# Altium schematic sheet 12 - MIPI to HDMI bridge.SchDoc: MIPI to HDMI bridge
size A3; PageSetup: Record=PageOptions¦CenterHorizontal=True¦CenterVertical=True¦PrintScale=0.70¦XCorrection=1.00¦YCorrection=1.00¦PrintKind=0¦BorderSize=5000000¦LeftOffset=0¦BottomOffset=0¦Orientation=2¦PaperLength=4200¦PaperWidth=2970¦Scale=100¦PaperSource=7¦PrintQuality=600¦MediaType=1¦DitherType=10¦PaperKind=A4¦PrintScaleMode=1; Author: Juan Anzola; SheetNumber: 12; SheetTotal: 20
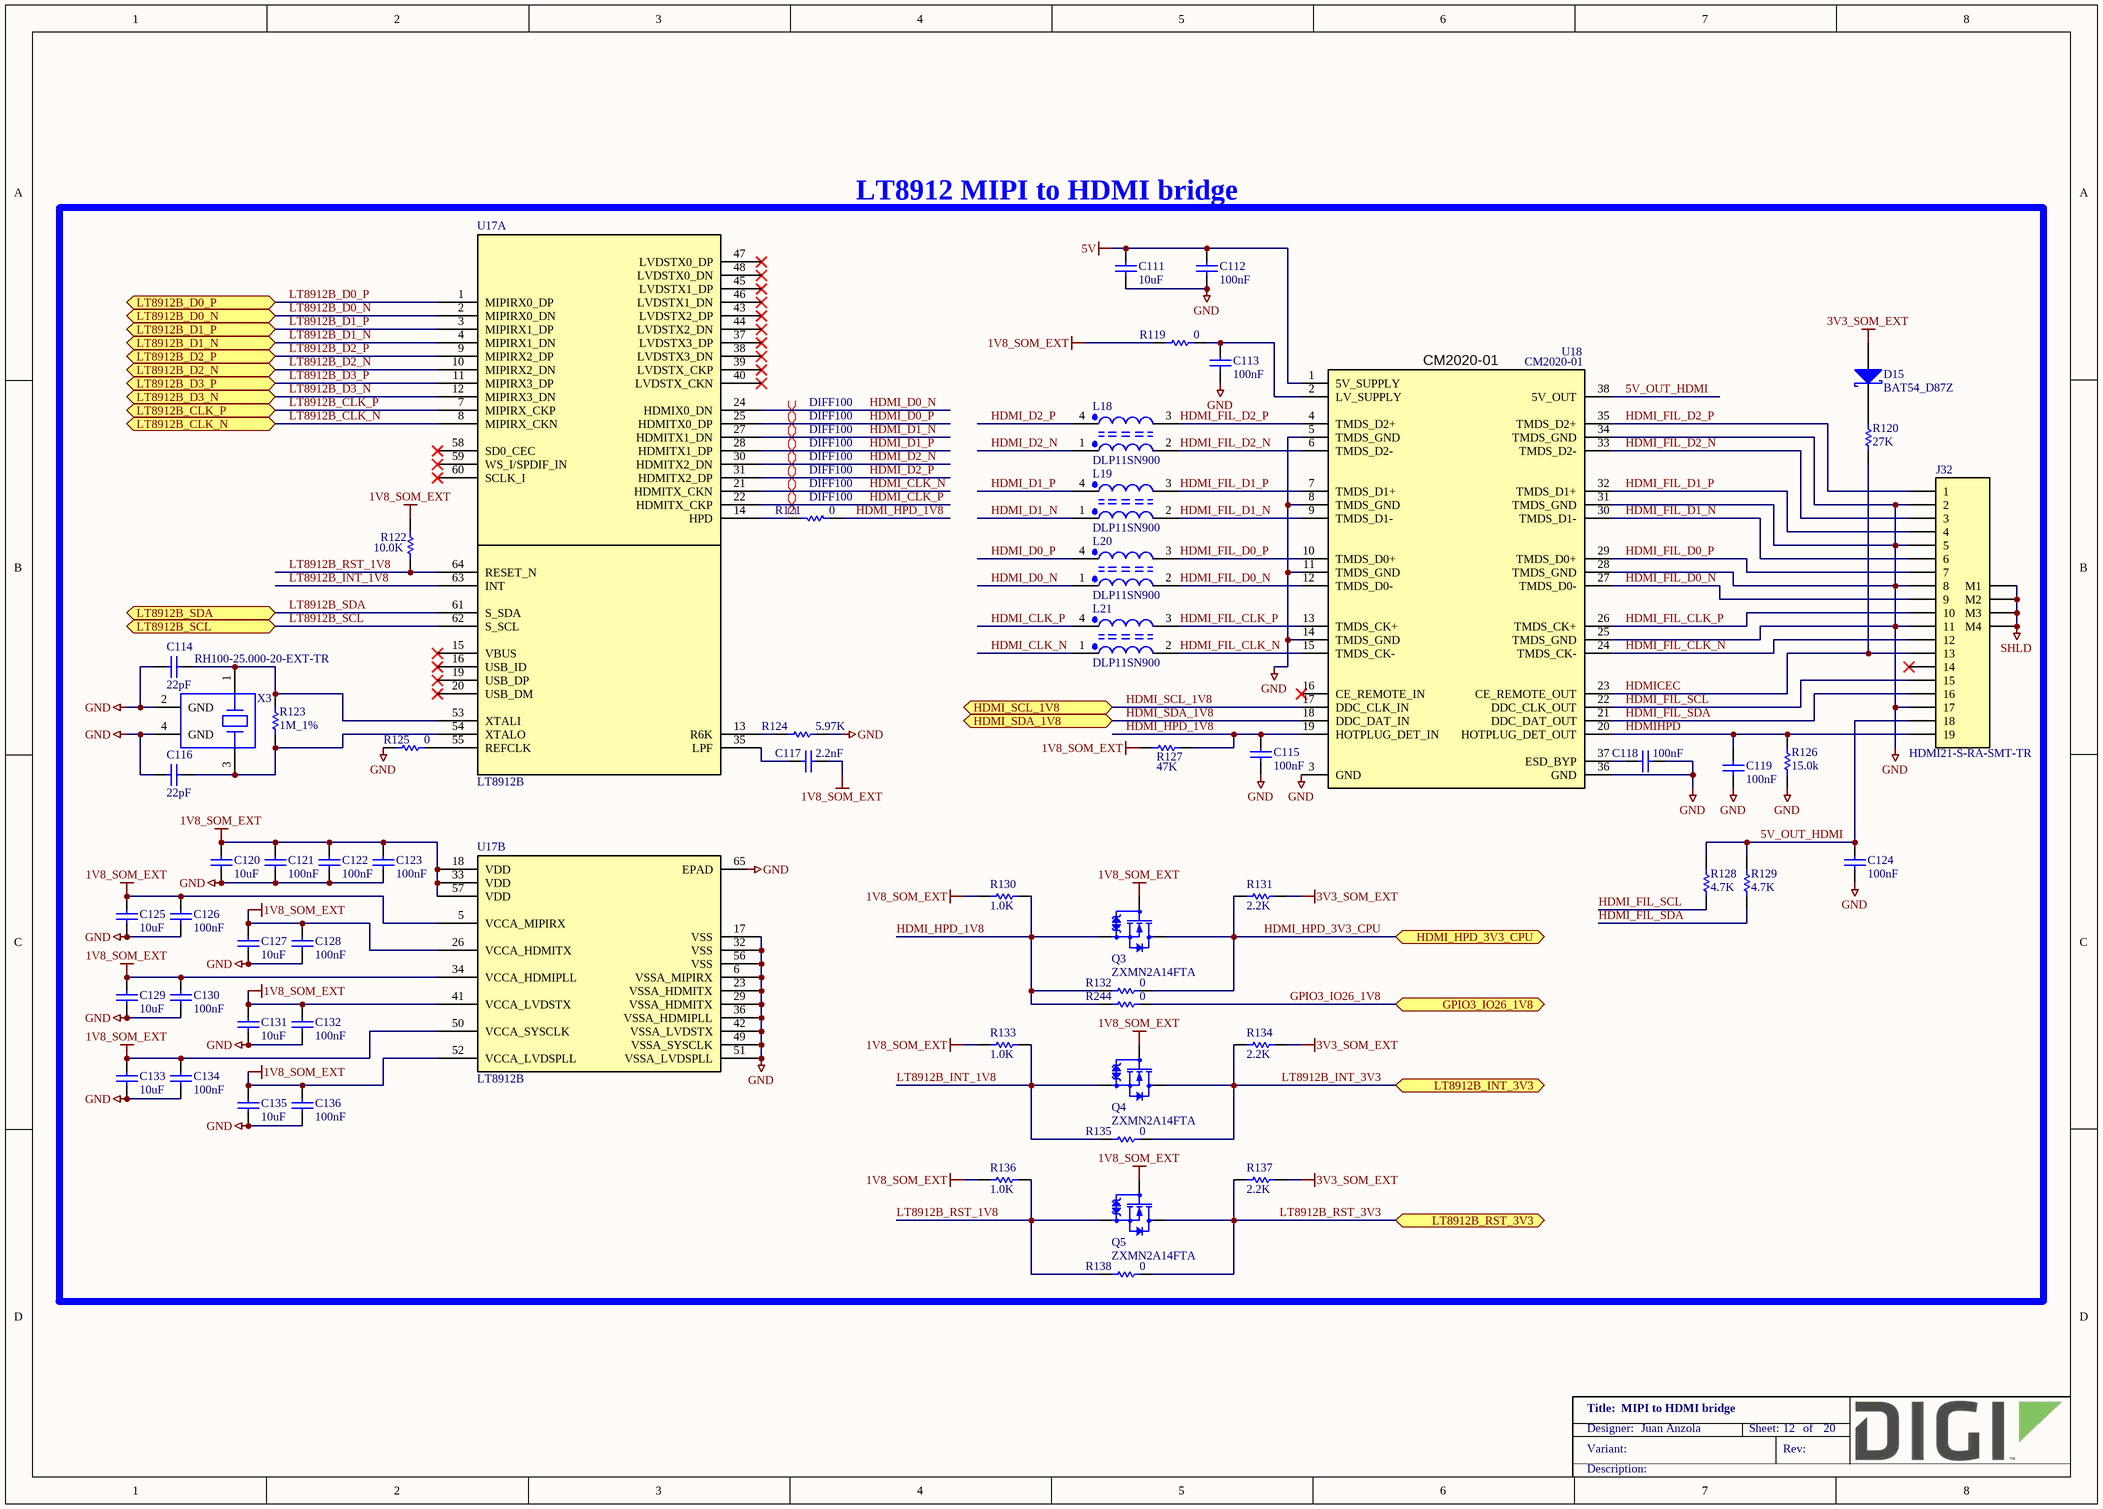
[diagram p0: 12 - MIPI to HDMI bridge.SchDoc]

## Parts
C111  10uF  [CAPC1005X55N]
C112  100nF  [CAPC1005X55N]
C113  100nF  [CAPC1005X55N]
C114  22pF  [CAPC1005X55N]
C115  100nF  [CAPC1005X55N]
C116  22pF  [CAPC1005X55N]
C117  2.2nF  [CAPC1608X90N]
C118  100nF  [CAPC1005X55N]
C119  100nF  [CAPC1005X55N]
C120  10uF  [CAPC1005X55N]
C121  100nF  [CAPC1005X55N]
C122  100nF  [CAPC1005X55N]
C123  100nF  [CAPC1005X55N]
C124  100nF  [CAPC1005X55N]
C125  10uF  [CAPC1005X55N]
C126  100nF  [CAPC1005X55N]
C127  10uF  [CAPC1005X55N]
C128  100nF  [CAPC1005X55N]
C129  10uF  [CAPC1005X55N]
C130  100nF  [CAPC1005X55N]
C131  10uF  [CAPC1005X55N]
C132  100nF  [CAPC1005X55N]
C133  10uF  [CAPC1005X55N]
C134  100nF  [CAPC1005X55N]
C135  10uF  [CAPC1005X55N]
C136  100nF  [CAPC1005X55N]
D15  BAT54_D87Z  [SOT95P240X110_AXK-3N]
J32  HDMI21-S-RA-SMT-TR  [HDMI21-S-RA-SMT-TR]
L18  DLP11SN900  [FIL_DLP11S]
L19  DLP11SN900  [FIL_DLP11S]
L20  DLP11SN900  [FIL_DLP11S]
L21  DLP11SN900  [FIL_DLP11S]
Q3  ZXMN2A14FTA  [SOT95P240X110_GSD-3N]
Q4  ZXMN2A14FTA  [SOT95P240X110_GSD-3N]
Q5  ZXMN2A14FTA  [SOT95P240X110_GSD-3N]
R119  0  [RESC1005X40N]
R120  27K  [RESC1005X40N]
R121  0  [RESC1005X40N]
R122  10.0K  [RESC1005X40N]
R123  1M_1%  [RESC1005X40N]
R124  5.97K  [RESC1005X40N]
R125  0  [RESC1005X40N]
R126  15.0k  [RESC1005X40N]
R127  47K  [RESC1005X40N]
R128  4.7K  [RESC1005X40N]
R129  4.7K  [RESC1005X40N]
R130  1.0K  [RESC1005X40N]
R131  2.2K  [RESC1005X40N]
R132  0  [RESC1005X40N]
R133  1.0K  [RESC1005X40N]
R134  2.2K  [RESC1005X40N]
R135  0  [RESC1005X40N]
R136  1.0K  [RESC1005X40N]
R137  2.2K  [RESC1005X40N]
R138  0  [RESC1005X40N]
R244  0  [RESC1005X40N]
U17  LT8912B  [QFN40P750X750X80-65T620N]  (parts A,B of 2)
U18  CM2020-01  [SOP50P640X120-38N]
X3  RH100-25.000-20-EXT-TR  [OSC210P320X250X90-4N]

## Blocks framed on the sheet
LT8912 MIPI to HDMI bridge: C111-C136 D15 J32 L18-L21 Q3-Q5 R119-R138 R244 U17 U18 X3

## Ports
GPIO3_IO26_1V8 (bidir), HDMI_HPD_3V3_CPU (bidir), HDMI_SCL_1V8 (bidir), HDMI_SDA_1V8 (bidir), LT8912B_CLK_N (bidir), LT8912B_CLK_P (bidir), LT8912B_D0_N (bidir), LT8912B_D0_P (bidir), LT8912B_D1_N (bidir), LT8912B_D1_P (bidir), LT8912B_D2_N (bidir), LT8912B_D2_P (bidir), LT8912B_D3_N (bidir), LT8912B_D3_P (bidir), LT8912B_INT_3V3 (bidir), LT8912B_RST_3V3 (bidir), LT8912B_SCL (bidir), LT8912B_SDA (bidir)

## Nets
1V8_SOM_EXT: C117.2 C120.2 C121.2 C122.2 C123.2 C125.2 C126.2 C127.2 C128.2 C129.2 C130.2 C131.2 C132.2 C133.2 C134.2 C135.2 C136.2 Q3.G Q4.G Q5.G R119.2 R122.1 R127.1 R130.2 R133.2 R136.2 U17.5(VCCA_MIPIRX) U17.18(VDD) U17.26(VCCA_HDMITX) U17.33(VDD) U17.34(VCCA_HDMIPLL) U17.41(VCCA_LVDSTX) U17.50(VCCA_SYSCLK) U17.52(VCCA_LVDSPLL) U17.57(VDD)
3V3_SOM_EXT: D15.A R131.2 R134.2 R137.2
5V: C111.2 C112.2 U18.1(5V_SUPPLY)
GND: C111.1 C112.1 C113.1 C114.1 C115.1 C116.1 C118.1 C119.1 C120.1 C121.1 C122.1 C123.1 C124.1 C125.1 C126.1 C127.1 C128.1 C129.1 C130.1 C131.1 C132.1 C133.1 C134.1 C135.1 C136.1 J32.2 J32.5 J32.8 J32.11 J32.17 R124.2 R125.1 R126.1 U17.6(VSSA_MIPIRX) U17.17(VSS) U17.23(VSSA_HDMITX) U17.29(VSSA_HDMITX) U17.32(VSS) U17.36(VSSA_HDMIPLL) U17.42(VSSA_LVDSTX) U17.49(VSSA_SYSCLK) U17.51(VSSA_LVDSPLL) U17.56(VSS) U17.65(EPAD) U18.3(GND) U18.5(TMDS_GND) U18.8(TMDS_GND) U18.11(TMDS_GND) U18.14(TMDS_GND) U18.25(TMDS_GND) U18.28(TMDS_GND) U18.31(TMDS_GND) U18.34(TMDS_GND) U18.36(GND) X3.2(GND) X3.4(GND)
SHLD: J32.M1 J32.M2 J32.M3 J32.M4
5V_OUT_HDMI: C124.2 J32.18 R128.1 R129.1 U18.38(5V_OUT)
GPIO3_IO26_1V8: R244.2 ; port GPIO3_IO26_1V8
HDMI_CLK_N: L21.1 U17.21(HDMITX_CKN)
HDMI_CLK_P: L21.4 U17.22(HDMITX_CKP)
HDMI_D0_N: L20.1 U17.24(HDMIX0_DN)
HDMI_D0_P: L20.4 U17.25(HDMITX0_DP)
HDMI_D1_N: L19.1 U17.27(HDMITX1_DN)
HDMI_D1_P: L19.4 U17.28(HDMITX1_DP)
HDMI_D2_N: L18.1 U17.30(HDMITX2_DN)
HDMI_D2_P: L18.4 U17.31(HDMITX2_DP)
HDMI_FIL_CLK_N: J32.12 L21.2 U18.15(TMDS_CK-) U18.24(TMDS_CK-)
HDMI_FIL_CLK_P: J32.10 L21.3 U18.13(TMDS_CK+) U18.26(TMDS_CK+)
HDMI_FIL_D0_N: J32.9 L20.2 U18.12(TMDS_D0-) U18.27(TMDS_D0-)
HDMI_FIL_D0_P: J32.7 L20.3 U18.10(TMDS_D0+) U18.29(TMDS_D0+)
HDMI_FIL_D1_N: J32.6 L19.2 U18.9(TMDS_D1-) U18.30(TMDS_D1-)
HDMI_FIL_D1_P: J32.4 L19.3 U18.7(TMDS_D1+) U18.32(TMDS_D1+)
HDMI_FIL_D2_N: J32.3 L18.2 U18.6(TMDS_D2-) U18.33(TMDS_D2-)
HDMI_FIL_D2_P: J32.1 L18.3 U18.4(TMDS_D2+) U18.35(TMDS_D2+)
HDMI_FIL_SCL: J32.15 R128.2 U18.22(DDC_CLK_OUT)
HDMI_FIL_SDA: J32.16 R129.2 U18.21(DDC_DAT_OUT)
HDMI_HPD_1V8: C115.2 Q3.S R121.1 R127.2 R130.1 R132.1 R244.1 U18.19(HOTPLUG_DET_IN)
HDMI_HPD_3V3_CPU: Q3.D R131.1 R132.2 ; port HDMI_HPD_3V3_CPU
HDMI_SCL_1V8: U18.17(DDC_CLK_IN) ; port HDMI_SCL_1V8
HDMI_SDA_1V8: U18.18(DDC_DAT_IN) ; port HDMI_SDA_1V8
HDMICEC: J32.13 R120.2 U18.23(CE_REMOTE_OUT)
HDMIHPD: C119.2 J32.19 R126.2 U18.20(HOTPLUG_DET_OUT)
LT8912B_CLK_N: U17.8(MIPIRX_CKN) ; port LT8912B_CLK_N
LT8912B_CLK_P: U17.7(MIPIRX_CKP) ; port LT8912B_CLK_P
LT8912B_D0_N: U17.2(MIPIRX0_DN) ; port LT8912B_D0_N
LT8912B_D0_P: U17.1(MIPIRX0_DP) ; port LT8912B_D0_P
LT8912B_D1_N: U17.4(MIPIRX1_DN) ; port LT8912B_D1_N
LT8912B_D1_P: U17.3(MIPIRX1_DP) ; port LT8912B_D1_P
LT8912B_D2_N: U17.10(MIPIRX2_DN) ; port LT8912B_D2_N
LT8912B_D2_P: U17.9(MIPIRX2_DP) ; port LT8912B_D2_P
LT8912B_D3_N: U17.12(MIPIRX3_DN) ; port LT8912B_D3_N
LT8912B_D3_P: U17.11(MIPIRX3_DP) ; port LT8912B_D3_P
LT8912B_INT_1V8: Q4.S R133.1 R135.1 U17.63(INT)
LT8912B_INT_3V3: Q4.D R134.1 R135.2 ; port LT8912B_INT_3V3
LT8912B_RST_1V8: Q5.S R122.2 R136.1 R138.1 U17.64(RESET_N)
LT8912B_RST_3V3: Q5.D R137.1 R138.2 ; port LT8912B_RST_3V3
LT8912B_SCL: U17.62(S_SCL) ; port LT8912B_SCL
LT8912B_SDA: U17.61(S_SDA) ; port LT8912B_SDA
NetC113_2: C113.2 R119.1 U18.2(LV_SUPPLY)
NetC114_2: C114.2 R123.2 U17.53(XTALI) X3.1
NetC116_2: C116.2 R123.1 U17.54(XTALO) X3.3
NetC117_1: C117.1 U17.35(LPF)
NetC118_2: C118.2 U18.37(ESD_BYP)
NetD15_K: D15.K R120.1
NetR121_2: R121.2 U17.14(HPD)
NetR124_1: R124.1 U17.13(R6K)
NetR125_2: R125.2 U17.55(REFCLK)

Not connected (* = marked no-connect by the designer): J32 14*; U17 15(VBUS)* 16(USB_ID)* 19(USB_DP)* 20(USB_DM)* 37(LVDSTX3_DP)* 38(LVDSTX3_DN)* 39(LVDSTX_CKP)* 40(LVDSTX_CKN)* 43(LVDSTX2_DP)* 44(LVDSTX2_DN)* 45(LVDSTX1_DP)* 46(LVDSTX1_DN)* 47(LVDSTX0_DP)* 48(LVDSTX0_DN)* 58(SD0_CEC)* 59(WS_I/SPDIF_IN)* 60(SCLK_I)*; U18 16(CE_REMOTE_IN)*

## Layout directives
differential pair; net class DIFF100; differential pair class DIFF100: HDMI_CLK_N, HDMI_CLK_P, HDMI_D0_N, HDMI_D0_P, HDMI_D1_N, HDMI_D1_P, HDMI_D2_N, HDMI_D2_P

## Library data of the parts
C111 C120 C125 C127 C129 C131 C133 C135 = 1001168: CAP CER 10UF 10V 20% X5R 0402; Part_Type: Capacitor; Manufacturer: Samsung; Manufacturer_Part_Number: CL05A106MP5NUNC; Digi_PN: 14050689; Component_Life_Cycle_State: Reviewed; Area: 0.95; Project: CCWMX6_SBC board
C112 C113 C115 C118 C119 C121-C124 C126 C128 C130 C132 C134 C136 = 1000006: CAP 100nF 16V 10% X7R 0402; Part_Type: Capacitor; Manufacturer: Murata; Manufacturer_Part_Number: GRM155R71C104KA88D; Component_Life_Cycle_State: CAD Reviewed; Area: 0.95; Project: KITT; Tolerance: 10; Digi_PN: 14050552
C114 C116 = 1001166: CAP CER 22PF 50V 5% NP0 0402; Part_Type: Capacitor; Manufacturer: Murata; Manufacturer_Part_Number: GRM1555C1H220JA01D; Note: 14050749 = Digi No. for GE WDNU; Digi_PN: 14050367; Component_Life_Cycle_State: Reviewed; Area: 0,95; Project: CCWMX6_SBC board; Temp_Coef: C0G, NP0
C117 = 1002727: CAP CER 2200PF 50V X7R 5% 0603; Part_Type: Capacitor; Manufacturer: Kemet; Manufacturer_Part_Number: C0603C222J5RACTU; Digi_PN: 14050443; Component_Life_Cycle_State: Pending; Area: 2,27
D15 = 1001169: DIODE SCHOTTKY 30V 0.2A SOT23-3; Part_Type: IC; Manufacturer: Fairchild Semiconductor; Digi_PN: 17050507; Component_Life_Cycle_State: Reviewed; Area: 8; Project: CCWMX6_SBC board
J32 = 1002870: CONN HDMI 2.1 RA SMT 48GBPS; Part_Type: Connector; Manufacturer: Adam Tech; Digi_PN: 18000903; Component_Life_Cycle_State: Pending
L18-L21 = 1001014: CHOKE COIL COMMON MODE 150MA SMD; Part_Type: Inductor; Manufacturer: Murata; Manufacturer_Part_Number: DLP11SN900HL2L; Component_Life_Cycle_State: Reviewed; Area: 3.94; Project: ResMed RF Test Interface Board; Digi_PN: 21000531
Q3-Q5 = 1002855: MOSFET N-CH 20V 3.4A SOT23-3; Part_Type: Transistor; Manufacturer: Diodes, Inc.; Digi_PN: 17000304; Component_Life_Cycle_State: Pending
R119 R121 R125 = 1000076: RES 0.0 OHM 1/10W 0402 SMD; Part_Type: Resistor; Manufacturer: Panasonic - ECG; Manufacturer_Part_Number: ERJ-2GE0R00X; Digi_PN: 13050387; Component_Life_Cycle_State: Proven; Area: 0,95; Project: Adjustable Foundation; Power_WV_SRF: 10
R120 = 1001153: RES 27.0K OHM 1/16W 1% 0402 SMD; Part_Type: Resistor; Manufacturer: Yageo; Manufacturer_Part_Number: RC0402FR-0727KL; Digi_PN: 13050609; Component_Life_Cycle_State: Reviewed; Area: 0.95; Project: CCWMX6_SBC board
R122 = 1000537: RES 10.0K OHM 1/10W 1% 0402 SMD; Part_Type: Resistor; Manufacturer: Panasonic - ECG; Manufacturer_Part_Number: ERJ-2RKF1002X; Component_Life_Cycle_State: CAD Reviewed; Area: 0.95; Project: KITT; Power_WV_SRF: 100; Digi_PN: 13051084
R123 = 1000971: RES 1.00M OHM 1/16W 1% 0402 SMD; Part_Type: Resistor; Manufacturer: Yageo; Manufacturer_Part_Number: RC0402FR-071ML; Note: 13051098 = Digi No. for GE WDNU; Digi_PN: 13050561; Component_Life_Cycle_State: Reviewed; Area: 0,95; Power_WV_SRF: 63; Tolerance: 1
R124 = 1002748: RES 5.97K OHM 0.1% 1/10W 0402; Part_Type: Resistor; Manufacturer: Vishay Dale; Manufacturer_Part_Number: TNPW04025K97BEED; Digi_PN: 13000099; Component_Life_Cycle_State: Created; Area: 0,95
R126 = 1000174: RES 15.0K OHM 1/10W 1% 0402 SMD; Part_Type: Resistor; Manufacturer: Panasonic - ECG; Manufacturer_Part_Number: ERJ-2RKF1502X; Component_Life_Cycle_State: CAD Reviewed; Area: 0.95; Project: KITT; Power_WV_SRF: 10; Digi_PN: 13050446
R127 = 1001155: RES 47.0K OHM 1/16W 1% 0402 SMD; Part_Type: Resistor; Manufacturer: Vishay Dale; Manufacturer_Part_Number: CRCW040247K0FKED; Digi_PN: 13050646; Component_Life_Cycle_State: Reviewed; Area: 0.95; Project: CCWMX6_SBC board
R128 R129 = 1000038: RES 4.7K OHM 1/10W 5% 0402 SMD; Part_Type: Resistor; Manufacturer: Panasonic - ECG; Manufacturer_Part_Number: ERJ-2GEJ472X; Component_Life_Cycle_State: Proven; Area: 0.95; Project: Adjustable Foundation; Power_WV_SRF: 100; Tolerance: 5; Digi_PN: 13050549
R130 R133 R136 = 1000079: RES 1.00K OHM 1/10W 1% 0402 SMD; Part_Type: Resistor; Manufacturer: Panasonic - ECG; Manufacturer_Part_Number: ERJ-2RKF1001X; Digi_PN: 13051085; Component_Life_Cycle_State: Proven; Area: 0,95; Project: Adjustable Foundation; Power_WV_SRF: 10
R131 R134 R137 = 1001156: RES 2.20K OHM 1/16W 1% 0402 SMD; Part_Type: Resistor; Manufacturer: Yageo; Manufacturer_Part_Number: RC0402FR-072K2L; Note: 13051099 = Digi No. for GE WDNU; Digi_PN: 13050699; Component_Life_Cycle_State: Reviewed; Area: 0,95
R132 R135 R138 R244 = 1000076: RES 0.0 OHM 1/10W 0402 SMD; Part_Type: Resistor; Manufacturer: Panasonic - ECG; Manufacturer_Part_Number: ERJ-2GE0R00X; Digi_PN: 13050387; Component_Life_Cycle_State: Proven; Area: 0,95; Power_WV_SRF: 10
U17 = 1002722: MIPI DSI BRIDGE TO LVDS/HDMI SINGLE CHANNEL; Part_Type: IC; Manufacturer: Lontium Semiconductor; Digi_PN: 16000199; Component_Life_Cycle_State: Reviewed; Area: 76,04
U18 = 1001125: IC HDMI XMITTER PORT P/I 38TSSOP; Manufacturer: On Semiconductor; Digi_PN: 16051861; Component_Life_Cycle_State: Reviewed; Area: 43; Project: CCWMX6_SBC board
X3 = 1001497: SMCRY,25MHZ 50PPM 20PF RH100 EXT; Part_Type: Crystals-Oscillators; Manufacturer: Raltron; Digi_PN: 20000285; Component_Life_Cycle_State: Reviewed; Area: 3,2; Project: CCWMX6_SBC board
